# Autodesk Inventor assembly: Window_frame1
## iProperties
Shininess: 64.0
Length Units: 11269
Angle Units: 11279
Time Units: 11290
Mass Units: 11283
Length Display Precision: 3
Angle Display Precision: 2
Compacted: True
Created: 2003-02
Part Number: Window_frame1
Document SubType Name: Assembly
Designer: hofer_a
Density: 0.0
Volumn: 0.0
Area: 0.0
PropertySet Name: Model Information
Control State: 0
Master: False
Checked Out: False
Author: hofer_a
